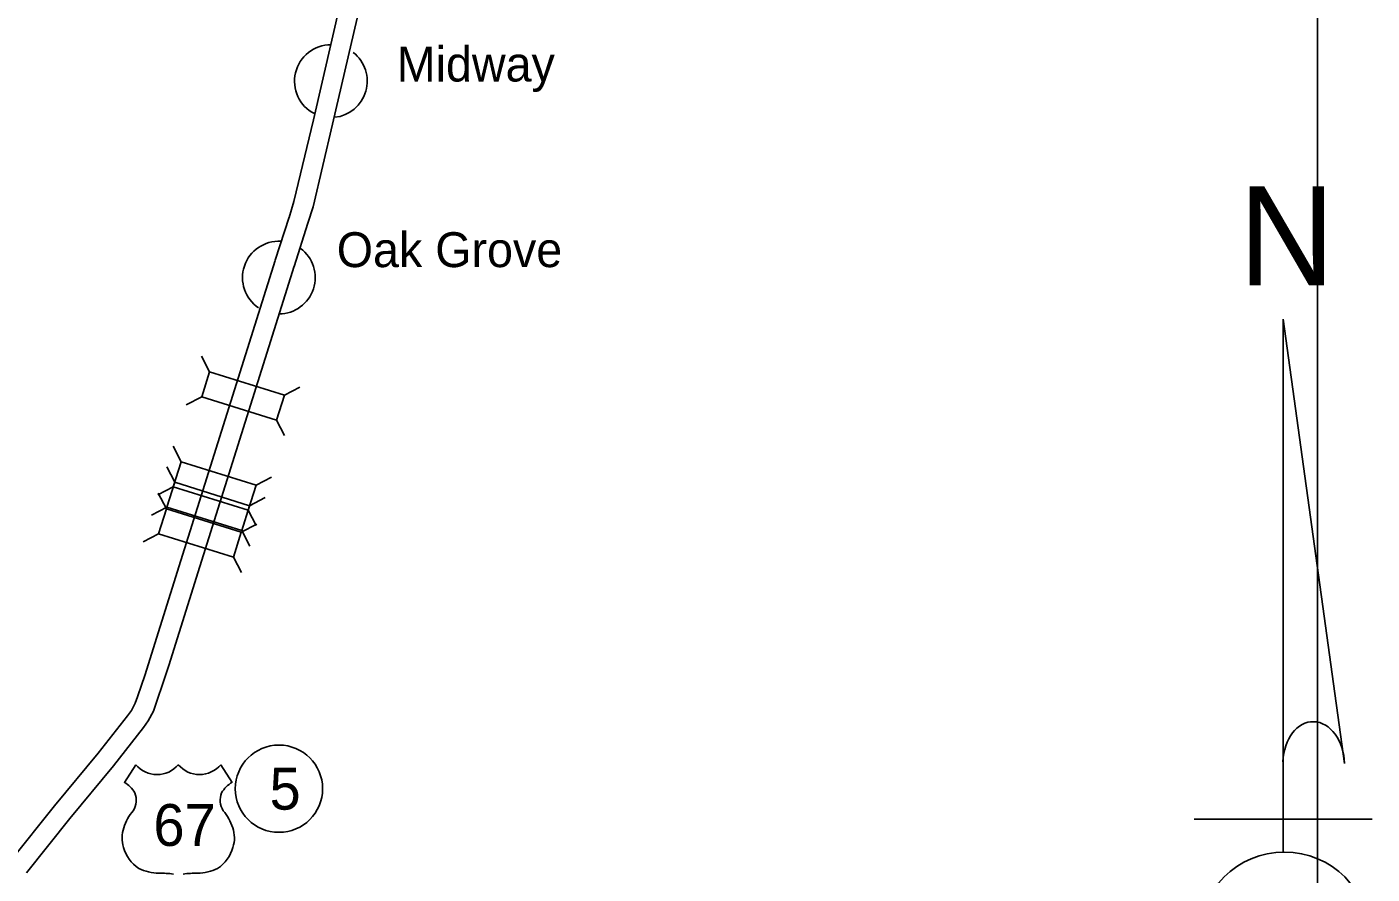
# Model space of a CAD drawing. Extents: x 1369979 to 1371646, y 379997 to 381064.
# Drawn here: x 1370321.9 to 1370481, y 380778 to 380878.2 of the extents above; entities that cross this region are included whole.
import ezdxf

# ---------------------------------------------------------------- set-up
doc = ezdxf.new("R2010")
doc.units = 0
for name, color, linetype in [('R_Border Notes', 7, 'Continuous'), ('R_Draft', 7, 'Continuous'), ('R_No Plot', 7, 'Continuous')]:
    doc.layers.add(name, color=color, linetype=linetype)

msp = doc.modelspace()

# ---------------------------------------------------------------- linework, layer by layer
at = {"layer": 'R_Border Notes'}
for p, q in [((1370343.49, 380837.42), (1370342.54, 380839.25)), ((1370352.35, 380834.64), (1370354.18, 380835.59)), ((1370342.57, 380834.47), (1370340.74, 380833.52)), ((1370351.42, 380831.69), (1370352.37, 380829.86)), ((1370340.14, 380826.77), (1370339.19, 380828.6)), ((1370339.38, 380824.36), (1370338.43, 380826.19)), ((1370349, 380823.99), (1370350.82, 380824.94)), ((1370339.21, 380823.82), (1370337.38, 380822.87)), ((1370338.39, 380821.21), (1370337.44, 380823.04)), ((1370338.45, 380821.41), (1370336.63, 380820.45)), ((1370348.24, 380821.57), (1370350.07, 380822.53)), ((1370348.07, 380821.04), (1370349.02, 380819.21)), ((1370337.46, 380818.26), (1370335.64, 380817.31)), ((1370347.25, 380818.43), (1370349.08, 380819.38)), ((1370347.31, 380818.62), (1370348.26, 380816.79)), ((1370346.32, 380815.48), (1370347.27, 380813.65)), ((1370334.77, 380790.93), (1370333.42, 380788.84)), ((1370344.82, 380790.93), (1370346.18, 380788.84))]:
    msp.add_line(p, q, dxfattribs=at)
for points in [[(1370369.87, 380934.41), (1370369.32, 380930.41), (1370368.75, 380926.32), (1370368.18, 380921.37), (1370367.89, 380919.66), (1370367.69, 380918.33), (1370367.16, 380915.92), (1370363.57, 380900.6), (1370360.15, 380886.11), (1370355.78, 380867.24), (1370353.47, 380857.56), (1370352.9, 380855.68)], [(1370372.26, 380934.59), (1370371.64, 380930.09), (1370371.07, 380926.02), (1370370.5, 380921.04), (1370370.21, 380919.3), (1370370, 380917.91), (1370369.44, 380915.39), (1370365.85, 380900.06), (1370362.43, 380885.58), (1370358.06, 380866.71), (1370355.74, 380856.94), (1370355.14, 380854.99)], [(1370351.28, 380850.61), (1370352.9, 380855.69)], [(1370353.51, 380849.89), (1370355.14, 380854.98)], [(1370340.1, 380815.09), (1370351.27, 380850.6)], [(1370342.34, 380814.39), (1370353.51, 380849.9)], [(1370336.43, 380803.36), (1370340.1, 380815.09)], [(1370338.67, 380802.66), (1370342.34, 380814.39)], [(1370320, 380779.59), (1370325.16, 380786.05), (1370330.32, 380792.29), (1370333.81, 380796.71), (1370334.26, 380797.36), (1370334.72, 380798.19), (1370334.97, 380798.94), (1370335.88, 380801.62), (1370336.43, 380803.36)], [(1370321.84, 380778.13), (1370326.98, 380784.57), (1370332.14, 380790.81), (1370335.69, 380795.32), (1370336.25, 380796.12), (1370336.88, 380797.25), (1370337.19, 380798.2), (1370338.11, 380800.88), (1370338.67, 380802.65)]]:
    msp.add_lwpolyline(points, dxfattribs=at)
for points in [[(1370342.57, 380834.47), (1370351.42, 380831.69), (1370352.35, 380834.64), (1370343.49, 380837.42)], [(1370349, 380823.99), (1370340.14, 380826.77), (1370339.21, 380823.82), (1370348.07, 380821.04)], [(1370348.24, 380821.57), (1370339.38, 380824.36), (1370338.45, 380821.41), (1370347.31, 380818.62)], [(1370347.25, 380818.43), (1370338.39, 380821.21), (1370337.46, 380818.26), (1370346.32, 380815.48)]]:
    msp.add_lwpolyline(points, close=True, dxfattribs=at)
msp.add_circle((1370351.71, 380788.09), 5.16, dxfattribs=at)
for centre, radius, start, end in [((1370357.85, 380871.8), 4.3, 89.8294, 243.3603), ((1370357.85, 380871.8), 4.3, 275.9308, 51.9989), ((1370351.7, 380848.56), 4.3, 86.9756, 236.2155), ((1370351.7, 380848.56), 4.3, 270.4971, 53.2746), ((1370337.29, 380793.05), 3.29, 220.075, 319.6701), ((1370342.31, 380793.05), 3.29, 220.3299, 319.925), ((1370331.65, 380785.81), 3.51, 30.7809, 59.9883), ((1370347.94, 380785.81), 3.51, 120.0117, 149.2191), ((1370332.42, 380786.73), 2.41, 328.8105, 21.2108), ((1370347.17, 380786.73), 2.41, 158.7892, 211.1895), ((1370338.72, 380781.8), 5.62, 138.9565, 162.6913), ((1370340.87, 380781.8), 5.62, 17.3087, 41.0435), ((1370336.87, 380782.26), 3.71, 160.9576, 197.3819), ((1370342.73, 380782.26), 3.71, 342.6181, 19.0424), ((1370337.47, 380782.27), 4.3, 195.1074, 237.1312), ((1370342.12, 380782.27), 4.3, 302.8688, 344.8926), ((1370337.55, 380783.62), 5.52, 244.0771, 269.5779), ((1370342.04, 380783.62), 5.52, 270.4221, 295.9229), ((1370337.68, 380768), 10.1, 81.1942, 90.9539), ((1370341.92, 380768), 10.1, 89.0461, 98.8058)]:
    msp.add_arc(centre, radius, start, end, dxfattribs=at)
at = {"layer": 'R_Draft'}
for p, q in [((1370470.5, 380843.66), (1370477.78, 380791.07)), ((1370470.5, 380780.59), (1370470.5, 380843.66)), ((1370459.97, 380784.49), (1370481.03, 380784.49))]:
    msp.add_line(p, q, dxfattribs=at)
msp.add_ellipse((1370474.13, 380790.96), major_axis=(-0.16, 5.06), ratio=0.719778, start_param=4.712385, end_param=7.768526, dxfattribs=at)
msp.add_ellipse((1370470.66, 380770.51), major_axis=(10.09, 0), ratio=0.999976, dxfattribs=at)
at = {"layer": 'R_No Plot'}
msp.add_lwpolyline([(1370052.8, 381020.95), (1370474.58, 381020.95), (1370474.58, 380650.53), (1370052.8, 380650.53)], close=True, dxfattribs=at)

# ---------------------------------------------------------------- texts
at = {"layer": 'R_Border Notes'}
for s, height, p in [('Midway', 4.125, (1370365.65, 380871.76)), ('Oak Grove', 4.125, (1370358.55, 380849.8)), ('5', 4.95, (1370350.6, 380785.61)), ('67', 4.95, (1370336.86, 380781.32))]:
    msp.add_text(s, height=height, dxfattribs=at).set_placement(p)
at = {"layer": 'R_Draft'}
msp.add_text('N', height=11.74, dxfattribs=at).set_placement((1370465.27, 380847.63))

doc.saveas('drawing.dxf')
